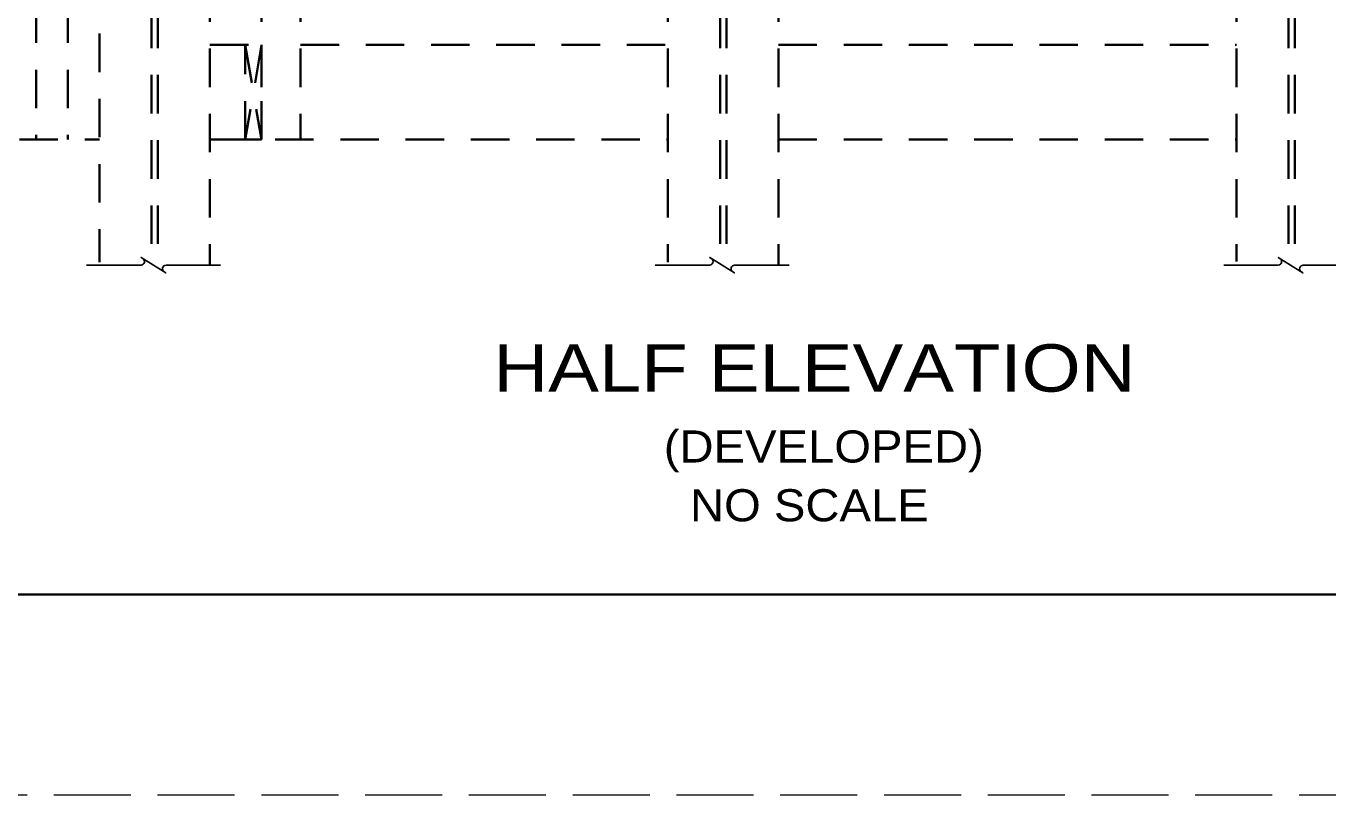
# Model space of a CAD drawing. Extents: x -6.4 to 73.1, y -66 to 0.
# Drawn here: x 41.656 to 46.524, y -66 to -63.125 of the extents above; entities that cross this region are included whole.
import ezdxf
from ezdxf.enums import TextEntityAlignment as Align

# ---------------------------------------------------------------- set-up
doc = ezdxf.new("R2010")
doc.units = 0
doc.header["$LTSCALE"] = 0.048
doc.linetypes.add('LONG_DASHED', pattern=[7.5, 6, -1.5])
doc.linetypes.add('MEDIUM_DASHED', pattern=[4.5, 3, -1.5])
for name, color, linetype, lineweight in [('1', 7, 'Continuous', 13), ('3', 7, 'Continuous', 35), ('4', 7, 'Continuous', 25), ('63', 7, 'LONG_DASHED', 13), ('8', 7, 'Continuous', 25)]:
    doc.layers.add(name, color=color, linetype=linetype, lineweight=lineweight)

msp = doc.modelspace()

# ---------------------------------------------------------------- linework, layer by layer
at = {"layer": '1', "lineweight": 35}
msp.add_lwpolyline([(35.75, -65.25), (67.25, -65.25), (67.25, -44.75), (35.75, -44.75)], close=True, dxfattribs=at)
at = {"layer": '3', "linetype": 'MEDIUM_DASHED'}
for p, q in [((41.812, -60.35992), (41.812, -63.54892)), ((41.69333, -62.06792), (41.69333, -63.54892)), ((41.93017, -62.1765), (41.93017, -64.00767)), ((42.34333, -62.23267), (42.34333, -64.0185)), ((42.53683, -62.23267), (42.53683, -63.54892)), ((42.68233, -62.23267), (42.68233, -63.54892)), ((44.05617, -62.23267), (44.05617, -64.00767)), ((44.46933, -62.23267), (44.46933, -64.0185)), ((46.18208, -62.23267), (46.18208, -64.00542)), ((42.34333, -63.19458), (42.53683, -63.19458)), ((42.47517, -63.54892), (42.47517, -63.19458)), ((42.47517, -63.19458), (42.53683, -63.54892)), ((42.53683, -63.19458), (42.47517, -63.54892)), ((42.53683, -63.54892), (42.53683, -63.19458)), ((42.68233, -63.19458), (44.05617, -63.19458)), ((44.46933, -63.19458), (46.18208, -63.19458)), ((41.14325, -63.54892), (41.93017, -63.54892)), ((42.34333, -63.54892), (44.05617, -63.54892)), ((42.39292, -63.54892), (42.57008, -63.54892)), ((44.46933, -63.54892), (46.18208, -63.54892))]:
    msp.add_line(p, q, dxfattribs=at)
at = {"layer": '63'}
msp.add_lwpolyline([(34, -66), (68, -66), (68, -44), (34, -44)], close=True, dxfattribs=at)
at = {"layer": '8', "linetype": 'MEDIUM_DASHED', "lineweight": 35}
for p, q in [((42.125, -60.37958), (42.125, -64.01408)), ((42.14867, -60.37958), (42.14867, -64.02892)), ((44.251, -60.37958), (44.251, -64.01408)), ((44.27467, -60.37958), (44.27467, -64.02892)), ((46.377, -60.37958), (46.377, -64.01408)), ((46.40058, -60.37958), (46.40058, -64.02892))]:
    msp.add_line(p, q, dxfattribs=at)
at = {"layer": '8'}
for p, q in [((42.08633, -64.01875), (41.88242, -64.01875)), ((42.38367, -64.01875), (42.17958, -64.01875)), ((44.21233, -64.01875), (44.00842, -64.01875)), ((44.50958, -64.01875), (44.30558, -64.01875)), ((46.33833, -64.01875), (46.13433, -64.01875)), ((46.63558, -64.01875), (46.43158, -64.01875))]:
    msp.add_line(p, q, dxfattribs=at)
for points in [[(42.17275, -64.04417), (42.1785, -64.04775), (42.08617, -63.98967), (42.09233, -63.99358)], [(44.29875, -64.04417), (44.3045, -64.04775), (44.21217, -63.98967), (44.21833, -63.99358)], [(46.42475, -64.04417), (46.4305, -64.04775), (46.33808, -63.98967), (46.34433, -63.99358)]]:
    msp.add_lwpolyline(points, dxfattribs=at)
for centre, start, end in [((42.08512, -64.00514), 275.32859, 57.86724), ((44.2111, -64.00514), 275.32859, 57.86724), ((46.33708, -64.00514), 275.32859, 57.86724), ((42.17962, -64.03236), 90, 240), ((44.3056, -64.03236), 90, 240), ((46.43158, -64.03236), 90, 240)]:
    msp.add_arc(centre, 0.01364, start, end, dxfattribs=at)

# ---------------------------------------------------------------- texts
at = {"layer": '4'}
for s, height, width, p in [('HALF ELEVATION', 0.1772, 1.2, (44.60408, -64.49183)), ('(DEVELOPED)', 0.12, 1.1, (44.63887, -64.75683)), ('NO SCALE', 0.12, 1.1, (44.58487, -64.97667))]:
    msp.add_text(s, height=height, dxfattribs=dict(at, width=width)).set_placement(p, align=Align.CENTER)

doc.saveas('drawing.dxf')
